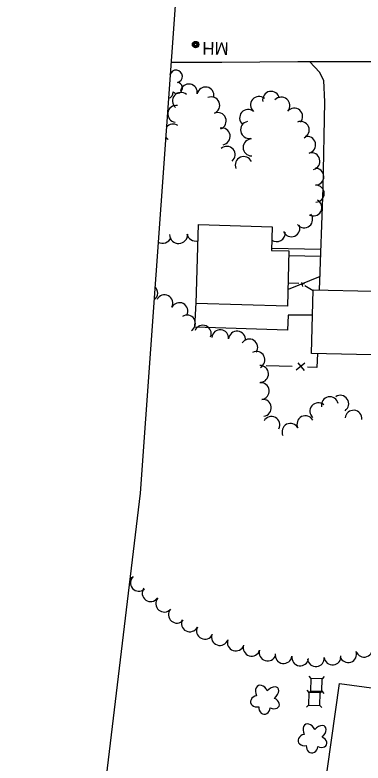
# Model space of a CAD drawing. Extents: x 189384 to 193282, y 256970 to 260388.
# Drawn here: x 190538.2 to 190703.8, y 259516.4 to 259872.4 of the extents above; entities that cross this region are included whole.
import ezdxf

# ---------------------------------------------------------------- set-up
doc = ezdxf.new("R2010")
doc.units = 0
for name, color, linetype in [('E_DRN_Grate', 7, 'Continuous'), ('E_DWY', 7, 'Continuous'), ('E_LAND_Vegetation', 7, 'Continuous'), ('E_MAP_Limits', 7, 'Continuous'), ('E_MISCPROP_HvyLine', 7, 'Continuous'), ('E_MISCPROP_Railing', 7, 'Continuous'), ('E_PATH_Sidewalk', 7, 'Continuous'), ('E_RDWY', 7, 'Continuous'), ('E_UTL_AboveGroundPipe', 7, 'Continuous')]:
    doc.layers.add(name, color=color, linetype=linetype)

# ---------------------------------------------------------------- blocks, each defined once
blk = doc.blocks.new('MHO_7')
at = {"layer": 'E_DRN_Grate'}
for centre, radius in [((0.04, -0.06), 1.5), ((0.04, -0.06), 1.22), ((0.04, -0.07), 0.968), ((0.01, -0.08), 0.605)]:
    blk.add_circle(centre, radius, dxfattribs=at)
blk = doc.blocks.new('MHT_5')
at = {"layer": 'E_DRN_Grate'}
blk.add_text('MH', height=6, rotation=0.0001, dxfattribs=at).set_placement((-5.61, -3.06))
blk = doc.blocks.new('PED')
at = {"layer": 'E_UTL_AboveGroundPipe'}
for p, q in [((-2.34, 2.71), (-3.29, 3.77)), ((3.06, 2.71), (4.02, 3.77)), ((-3.29, -4.35), (-2.34, -3.29)), ((4.02, -4.35), (3.06, -3.29))]:
    blk.add_line(p, q, dxfattribs=at)
blk.add_lwpolyline([(-2.34, -3.29), (3.06, -3.29), (3.06, 2.71), (-2.34, 2.71)], close=True, dxfattribs=at)
blk = doc.blocks.new('TREE')
at = {"layer": 'E_LAND_Vegetation'}
for centre, major_axis, ratio in [((-1.07, 3.38), (0.91, -3.32), 0.782863), ((2.88, 1.66), (-3.52, -1.95), 0.691916), ((-3.74, -0.07), (3.29, -0.08), 0.832022), ((-1.48, -3.66), (1.2, 3.24), 0.716896), ((2.54, -2.64), (-3.34, 3.06), 0.560249)]:
    blk.add_ellipse(centre, major_axis=major_axis, ratio=ratio, start_param=1.570796, end_param=4.712389, dxfattribs=at)

msp = doc.modelspace()

# ---------------------------------------------------------------- linework, layer by layer
at = {"layer": 'E_DWY'}
for points in [[(190683.12, 259741.58), (190684.92, 259790.24), (190685.69, 259831.16), (190685.12, 259841.31), (190683.15, 259845.28), (190678.52, 259850.17)], [(190670.76, 259448.61), (190677.52, 259447.58), (190692.62, 259554.31), (190721.93, 259550.33)]]:
    msp.add_lwpolyline(points, dxfattribs=at)
at = {"layer": 'E_LAND_Vegetation'}
for centre, radius, start, end in [((190614.9, 259843.22), 2.97, 282.1075, 165.0807), ((190609.07, 259843.73), 2.97, 4.4566, 6.9891), ((190615.29, 259837.71), 2.61, 226.8127, 84.7453), ((190620.94, 259835.54), 4.03, 349.8163, 169.8009), ((190628.88, 259834.11), 4.03, 349.8163, 169.8009), ((190610.73, 259835.56), 2.78, 280.0294, 5.1156), ((190617.19, 259831.55), 4.03, 49.8329, 229.8176), ((190654.33, 259829.61), 4.03, 49.8312, 229.8159), ((190660.09, 259832.05), 4.03, 10.9547, 190.9394), ((190631.58, 259829.42), 4.03, 292.4023, 112.387), ((190664.96, 259829.33), 4.03, 319.0891, 139.0738), ((190614.97, 259825.36), 4.03, 82.3047, 262.2894), ((190649.13, 259823.45), 4.03, 49.8312, 229.8159), ((190671.06, 259824.04), 4.03, 319.0891, 139.0738), ((190634.66, 259821.96), 4.03, 292.4023, 112.387), ((190613.38, 259816.5), 4.03, 55.185, 141.5566), ((190649.57, 259817.72), 4.03, 101.3185, 281.3031), ((190674.18, 259817.72), 4.03, 293.6106, 113.5953), ((190636.58, 259814.64), 4.03, 280.03, 100.0147), ((190608.77, 259809.87), 4.03, 55.185, 74.6084), ((190613.38, 259816.5), 4.03, 210.2289, 235.1696), ((190650.8, 259809.38), 4.03, 90.5971, 270.5818), ((190677.23, 259810.62), 4.03, 284.6166, 104.6013), ((190638.91, 259805.89), 4.03, 310.8516, 130.8362), ((190647.03, 259801.03), 4.03, 23.2748, 203.2594), ((190679.27, 259802.81), 4.03, 284.6166, 104.6013), ((190681.13, 259795.47), 4.03, 271.327, 91.3117), ((190681.32, 259787.41), 4.03, 271.327, 91.3117), ((190680.17, 259780.8), 4.03, 241.1438, 61.1285), ((190675.82, 259775.17), 4.03, 218.9902, 38.9748), ((190669.75, 259770.92), 4.03, 202.6557, 22.6403), ((190608.41, 259768.14), 4.35, 240.8703, 338.2548), ((190616.08, 259768.02), 4.35, 181.8192, 1.8039), ((190624.3, 259769.16), 4.35, 191.1737, 282.8313), ((190662.75, 259768.57), 4.03, 233.4566, 5.917), ((190602.13, 259740.11), 4, 308.5163, 48.7237), ((190609.37, 259735.19), 4, 332.6386, 152.6233), ((190616.47, 259731.51), 4, 332.6386, 152.6233), ((190620.08, 259725.59), 4, 302.8127, 122.7974), ((190627.62, 259720.76), 4, 337.5751, 157.5597), ((190635.89, 259718.64), 4, 354.7537, 174.7383), ((190643.86, 259717.9), 4, 354.7537, 174.7383), ((190649.69, 259714.2), 4, 326.4626, 146.4473), ((190653.12, 259708.28), 4, 297.4556, 117.4403), ((190654.83, 259701.6), 4, 272.2293, 92.2139), ((190655.16, 259693.43), 4, 277.1702, 97.1549), ((190693.01, 259687.43), 4, 303.7174, 123.7021), ((190656.16, 259685.49), 4, 277.1702, 97.1549), ((190682.55, 259683.87), 4, 49.8341, 229.8188), ((190687.98, 259686.74), 4, 10.6864, 190.6711), ((190699.25, 259680.29), 4, 354.7081, 174.6928), ((190660.25, 259677.34), 4, 332.0096, 151.9943), ((190676.37, 259677.72), 4, 27.214, 207.1987), ((190669.26, 259674.06), 4, 27.214, 207.1987), ((190591.86, 259608.2), 4, 284.5735, 311.2878), ((190597.14, 259602.19), 4, 131.3031, 311.2878), ((190602.73, 259597.27), 4, 144.8012, 324.7859), ((190609.23, 259592.27), 4, 139.125, 319.1097), ((190615.27, 259587.03), 4, 139.125, 319.1097), ((190621.4, 259582.88), 4, 153.8717, 333.8563), ((190628.58, 259579.36), 4, 153.8717, 333.8563), ((190635.7, 259576.38), 4, 161.1521, 341.1368), ((190643.27, 259573.79), 4, 161.1521, 341.1368), ((190650.8, 259571.31), 4, 163.0296, 343.0142), ((190658.45, 259568.97), 4, 163.0296, 343.0142), ((190704.31, 259570.83), 4, 198.8685, 18.8531), ((190666.02, 259567.78), 4, 172.135, 352.1196), ((190673.94, 259566.68), 4, 172.135, 352.1196), ((190681.38, 259566.3), 4, 185.757, 5.7416), ((190689.34, 259567.1), 4, 185.757, 5.7416), ((190696.74, 259568.25), 4, 198.8685, 18.8531)]:
    msp.add_arc(centre, radius, start, end, dxfattribs=at)
at = {"layer": 'E_MAP_Limits'}
msp.add_lwpolyline([(190622.49, 259989.85), (190597.72, 259644.89), (190538.23, 259147.8)], dxfattribs=at)
at = {"layer": 'E_MISCPROP_HvyLine'}
for points in [[(190667.83, 259733.91), (190667.83, 259733.91), (190624.42, 259735.14), (190625.48, 259772.64), (190625.48, 259772.64), (190660.52, 259771.65), (190660.52, 259771.65), (190660.52, 259771.65), (190660.2, 259760.36), (190660.2, 259760.36), (190668.57, 259760.13), (190668.57, 259760.13)], [(190708.48, 259741.02), (190708.48, 259741.02), (190707.8, 259710.68), (190707.8, 259710.68), (190679.36, 259711.31), (190680.04, 259741.65), (190680.04, 259741.65), (190708.48, 259741.02)]]:
    msp.add_lwpolyline(points, close=True, dxfattribs=at)
at = {"layer": 'E_MISCPROP_Railing'}
for p, q in [((190675.18, 259743.15), (190674.77, 259745.05)), ((190675.97, 259744.4), (190673.76, 259743.95)), ((190676.2, 259706.79), (190672, 259703.35)), ((190675.9, 259703.23), (190672.93, 259706.82))]:
    msp.add_line(p, q, dxfattribs=at)
for points in [[(190673.32, 259744.61), (190668.13, 259744.78)], [(190680.03, 259741.2), (190676.05, 259743.45)], [(190682.21, 259711.24), (190681.83, 259704.7), (190677.42, 259704.84)], [(190670.17, 259705.06), (190657.71, 259705.45)]]:
    msp.add_lwpolyline(points, dxfattribs=at)
at = {"layer": 'E_PATH_Sidewalk'}
for points in [[(190683.83, 259760.79), (190660.23, 259761.22)], [(190683.71, 259757.42), (190668.5, 259757.75)], [(190683.36, 259747.97), (190668.16, 259741.76), (190668.05, 259741.76)], [(190679.77, 259729.54), (190668.23, 259729.58), (190667.87, 259722.47), (190623.79, 259723.9), (190624.43, 259735.52)]]:
    msp.add_lwpolyline(points, dxfattribs=at)
at = {"layer": 'E_RDWY'}
msp.add_lwpolyline([(190977.43, 259841.11), (190974.92, 259843.83), (190971.99, 259845.42), (190966.37, 259847.83), (190958.04, 259850.14), (190948.14, 259851.49), (190933.02, 259852), (190911.04, 259852.07), (190866.77, 259851.65), (190832.26, 259851.54), (190796.71, 259851.25), (190757.73, 259850.8), (190715.01, 259850.07), (190672.84, 259850.18), (190636.69, 259849.75), (190613, 259849.81), (190612.43, 259849.8)], dxfattribs=at)

# ---------------------------------------------------------------- block references
at = {"layer": 'E_DRN_Grate'}
for name, p, rotation in [('MHO_7', (190624.18, 259858.3), 179.11539862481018), ('MHT_5', (190634.24, 259856.45), 179.11539844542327)]:
    msp.add_blockref(name, p, dxfattribs=dict(at, rotation=rotation))
at = {"layer": 'E_LAND_Vegetation'}
for p, rotation in [((190657.17, 259546.66), 86.03298025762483), ((190679.75, 259528.23), 86.0329798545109)]:
    msp.add_blockref('TREE', p, dxfattribs=dict(at, rotation=rotation))
at = {"layer": 'E_UTL_AboveGroundPipe'}
for p, xscale, yscale, rotation in [((190681.93, 259553.32), 0.9999978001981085, 0.9999978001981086, 178.52108218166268), ((190680.96, 259546.64), 0.9999978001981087, 0.9999978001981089, 178.52108219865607)]:
    msp.add_blockref('PED', p, dxfattribs=dict(at, xscale=xscale, yscale=yscale, rotation=rotation))

doc.saveas('drawing.dxf')
